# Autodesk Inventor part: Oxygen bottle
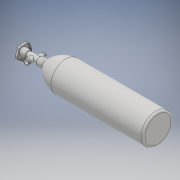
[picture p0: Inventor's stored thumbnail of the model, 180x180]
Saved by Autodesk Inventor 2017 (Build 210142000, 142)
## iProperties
Created: 2020-03
Part Number: Oxygen bottle
Material: Generic
Document SubType Name: Modeling
Designer: user
Density: 1 g/cm^3
Appearance: Default
Author: user
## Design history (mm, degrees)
sketch "Sketch1"
  geometry: L1 (0, 0)-(0, 65); L2 (10, 75)-(461.493, 75); L3 (560, 20)-(560, 0); L4 (560, 0)-(0, 0); A1 r 146.454 centre (444.859, -70.506) between (560, 20) and (461.493, 75); A2 r 10 centre (10, 65) between (10, 75) and (0, 65); 1 further point
  constraints: 8 end point, 4 point on circle, 3 perpendicular, 2 centre point, 2 point on line, 2 tangent, 1 vertical
  dimensions: "d0" = 75 distance of L1.start point (0, 75); "d2" = 560 distance from line of point (0, 75) L3; "d6" = 10 radius of A2; "d8" = 20 distance of L3.start L3.end
revolve "Revolution1" sketch "Sketch1" stored, may be unused: angle "d7" = 90 deg
sketch "Sketch2"
  geometry: C1 r 20 at (0, 0); C2 r 20 at (0, 0) reference; 1 further point
  constraints: 1 centre point, 1 coincident, 1 concentric
extrude "Extrusion1" join sketch "Sketch2" distance "d9" = 30; taper "d10" = 0 deg
workplane "Work Plane1"
sketch "Sketch3"
  geometry: C1 r 16 at (0, 0); 1 further point
  constraints: 1 centre point, 1 coincident
  dimensions: "d12" = 32 diameter of C1
loft "Loft1" sketch "Sketch3" dims "d13" = 10, "d14" = 90 deg, "d15" = 0, "d16" = 90 deg
  node "Edges1"
sketch "Sketch4"
  geometry: C1 r 14 at (0, 0); 1 further point
  constraints: 1 centre point, 1 coincident
  dimensions: "d17" = 28 diameter of C1
extrude "Extrusion2" join sketch "Sketch4" distance "d18" = 55; taper "d19" = 0 deg
sketch "Sketch5"
  geometry: C1 r 11.646 at (607.574, 0); 1 further point
  constraints: 1 centre point
extrude "Extrusion3" join sketch "Sketch5" distance "d20" = 30; taper "d21" = 0 deg
sketch "Sketch6"
  geometry: C1 r 12.412 at (620.618, 0); 1 further point
  constraints: 1 centre point
extrude "Extrusion4" join sketch "Sketch6" distance "d22" = 40; taper "d23" = 0 deg
sketch "Sketch7"
  geometry: C1 r 17.5 at (0, 0); 1 further point
  constraints: 1 centre point, 1 coincident
  dimensions: "d24" = 35 diameter of C1
extrude "Extrusion5" join sketch "Sketch7" distance "d25" = 20; taper "d26" = 0 deg
sketch "Sketch8"
  geometry: L1 (-35.907, 7.641)-(-18.363, 31.789); L2 (-3.829, 36.511)-(24.558, 27.288); L3 (33.541, 14.924)-(33.541, -14.924); L4 (24.558, -27.288)-(-3.829, -36.511); L5 (-18.363, -31.789)-(-35.907, -7.641); C1 r 14 at (0, 0) reference; A1 r 13 centre (-7.846, -24.147) between (-18.363, -31.789) and (-3.829, -36.511); A2 r 13 centre (20.541, -14.924) between (24.558, -27.288) and (33.541, -14.924); A3 r 13 centre (20.541, 14.924) between (33.541, 14.924) and (24.558, 27.288); A4 r 13 centre (-7.846, 24.147) between (-3.829, 36.511) and (-18.363, 31.789); A5 r 13 centre (-25.39, 0) between (-35.907, 7.641) and (-35.907, -7.641); 7 further points
  constraints: 10 end point, 10 point on circle, 10 point on line, 10 tangent, 5 centre point, 4 equal radius, 1 coincident, 11 other
  dimensions: "d27" = 75 distance from line of L3 point (-41.459, 0); "d28" = 13 radius of A1
extrude "Extrusion6" join sketch "Sketch8" distance "d29" = 12; taper "d30" = 0 deg
shell "Shell1" dims "d31" = 3
sketch "Sketch9"
  geometry: C1 r 14.5 at (0, 0) reference; C2 r 17.5 at (0, 0); 1 further point
  constraints: 1 centre point, 1 coincident
extrude "Extrusion7" join sketch "Sketch9" stored distance "d32" = 12; taper "d33" = 0 deg
fillet "Fillet1" dims "d34" = 3
sketch "Sketch10"
  geometry: C1 r 6.35 at (0, 0); 1 further point
  constraints: 1 centre point
  dimensions: "d35" = 12.7 diameter of C1
extrude "Extrusion8" join sketch "Sketch10" distance "d36" = 12; taper "d37" = 0 deg
fillet "Fillet2" dims "d38" = 1.5
thread "Thread1" dims "d39" = 7, "d40" = 0
sketch "Sketch11"
  geometry: C1 r 5.5 at (0, 0); 1 further point
  constraints: 1 centre point
  dimensions: "d41" = 11 diameter of C1
extrude "Extrusion9" cut sketch "Sketch11" distance "d42" = 12; taper "d43" = 0 deg
thread "Thread2" dims "d44" = 15, "d45" = 0
sketch "Sketch12"
  geometry: C1 r 10.281 at (0, 0); 1 further point
  constraints: 1 centre point
extrude "Extrusion10" cut sketch "Sketch12" distance "d46" = 40; taper "d47" = 0 deg
body "Solid1"
other parameters: "d11" = 4
